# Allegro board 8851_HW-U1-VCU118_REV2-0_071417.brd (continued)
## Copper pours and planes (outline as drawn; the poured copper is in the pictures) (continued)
(no net) on TOP: 177.19,71.52 177.19,70.35 176.97,70.12 174.89,70.12 174.65,70.36 174.65,71.83 174.88,72.06 176.66,72.06
(no net) on BOTTOM: 46.3,48.76 46.3,50.44 46.09,50.64 43.5,50.64 43.41,50.55 43.41,48.66 43.46,48.61 46.15,48.61
(no net) on BOTTOM: 45.01,21.77 43.5,21.77 43.41,21.67 43.41,19.78 43.46,19.73 45.46,19.73 45.77,20.04 45.77,21.23 45.67,21.34 45.21,21.34 45.06,21.49 45.06,21.71
(no net) on BOTTOM: 187.39,51.67 181.83,51.67 181.83,49.07 187.39,49.07
(no net) on BOTTOM: 144,127.21 145.92,127.21 146.3,127.59 146.3,128.95 146.02,129.23 145.3,129.23 144.88,129.64 144.88,130.66 144.53,131.01 143.38,131.01 143.21,130.84 143.21,127.91 143.36,127.76 143.98,127.76 143.98,127.23
(no net) on BOTTOM: 195.52,16.69 194.62,15.78 191.98,15.78 191.98,14.01 192.12,13.86 196.98,13.86 197.44,14.32 197.44,16.38 197.13,16.69
(no net) on BOTTOM: 21.46,87.54 21.47,87.54 21.47,90.16 21.38,90.24 18.64,90.24 18.54,90.15 18.54,87.74 18.75,87.54
(no net) on BOTTOM: 49.36,100.55 51.1,100.55 51.43,100.88 51.43,103.01 51.14,103.3 49.38,103.3 49.11,103.02 49.11,100.81
(no net) on BOTTOM: 140.49,16.21 140.49,14.39 142.58,14.39 142.84,14.65 142.84,16.14 142.65,16.33 140.62,16.33
(no net) on BOTTOM: 42.51,33.1 40.16,33.1 40.11,33.06 40.11,18.39 40.2,18.3 42.94,18.3 43.22,18.59 43.22,19.2 42.81,19.61 42.01,19.61 41.83,19.8 41.75,19.8 41.75,31.76 42.05,32.05 42.76,32.05 42.89,32.18 42.89,32.72
(no net) on BOTTOM: 140.28,126.37 140.28,116.47 137.24,116.47 137.24,126.37
(no net) on BOTTOM: 184.95,56.96 184.95,60.77 185.07,60.89 185.33,60.89 185.58,61.15 185.58,63.05 185.71,63.18 186.22,63.18 186.47,62.93 186.47,60.26 186.98,59.75 186.98,58.86 187.61,58.23 187.61,56.96 188.97,56.96 189.99,55.93 189.99,53.87 188.65,52.52 178.63,52.52 178.1,53.05 178.1,55.42 178.38,55.7 180.97,55.7 182.22,56.96
(no net) on BOTTOM: 42.51,58.68 40.16,58.68 40.11,58.63 40.11,44.23 40.31,44.03 42.94,44.03 43.22,44.31 43.22,44.72 42.77,45.18 41.95,45.18 41.75,45.37 41.75,57.34 42.05,57.63 42.76,57.63 42.89,57.76 42.89,58.29
(no net) on BOTTOM: 139.43,24.96 137.09,24.96 137.09,28.53 137.26,28.7 138.47,28.7 138.47,27.29 138.59,27.17 139.22,27.17 139.43,26.96
(no net) on BOTTOM: 150.34,128.63 150.34,130.1 150.25,130.19 147.28,130.19 147.28,128.63 147.56,128.35 150.06,128.35
(no net) on BOTTOM: 156.23,143.36 156.23,136.75 156.21,136.75 156.21,133.31 155.48,132.58 153.21,132.58 152.46,133.33 152.46,134.67 153.69,135.9 153.69,138.78 150.7,138.78 150.55,138.93 150.55,140.46 150.9,140.81 151.79,140.81 152.42,141.45 153.69,141.45 153.69,143.12 154.25,143.68 155.91,143.68
(no net) on BOTTOM: 59.6,135.74 59.6,133.98 60.08,133.51 66.6,133.51 66.6,133.53 66.8,133.53 67.33,134.06 67.33,135.4 65.98,136.74 57.2,136.74 57.03,136.58 57.03,135.53 57.4,135.53 57.61,135.74
(no net) on BOTTOM: 232.09,60.92 228.51,60.92 227.46,59.87 227.46,58.95 228.89,57.52 228.89,54.94 228.93,54.94 230.96,52.91 232.87,52.91 233.91,53.95 233.91,59.1
(no net) on BOTTOM: 25.83,139.09 25.83,140.79 25.69,140.93 25.69,141.62 25.63,141.68 24.79,141.68 24.26,141.15 23.72,141.15 23.63,141.06 23.63,138.8 24.69,137.74 25.22,137.74 25.32,137.85 25.32,138.58
(no net) on BOTTOM: 233.05,134.9 233.05,142.09 231.75,143.38 228.63,143.38 227.48,142.24 227.48,139.55 227.13,139.19 222.45,139.19 221.54,140.11 221.54,142.87 221.23,143.18 219.23,143.18 218.82,142.78 218.82,138.43 212.57,132.18 212.57,129.95 213.8,128.72 216.37,128.72 219.41,131.75 222.17,131.75 222.43,132 222.43,132.82 223.19,133.58 231.73,133.58
(no net) on BOTTOM: 214.25,149.51 214.25,145.06 214.48,144.83 217.71,144.83 218.52,144.02 221.26,144.02 221.95,143.33 221.95,140.92 223.27,139.6 225.96,139.6 227.08,140.72 227.08,142.39 228.45,143.76 232.26,143.76 232.89,144.4 232.89,148.61 232.11,149.4 217.92,149.4 217.55,149.77 214.5,149.77
(no net) on BOTTOM: 191.11,44.7 191.11,36.17 190.93,35.99 188.06,35.99 187.58,36.47 187.58,43.11 189.56,45.08 190.73,45.08
(no net) on BOTTOM: 46.3,52.06 46.3,53.74 46.09,53.94 43.5,53.94 43.41,53.85 43.41,51.96 43.46,51.91 46.15,51.91
(no net) on BOTTOM: 61.17,128.31 60.86,128.62 58.04,128.62 57.48,128.07 57.48,123.77 58.37,122.88 60.97,122.88 61.17,123.08
(no net) on BOTTOM: 5.14,126.69 5.06,126.62 5.06,124.44 5.17,124.33 7.24,124.33 7.49,124.59 7.49,126.31 7.11,126.69
(no net) on BOTTOM: 45.45,28.37 43.5,28.37 43.41,28.28 43.41,26.38 43.46,26.34 45.61,26.34 45.75,26.48 45.75,28.07
(no net) on BOTTOM: 180.58,15.66 180.58,13.98 180.8,13.76 189.91,13.76 190.28,14.13 190.28,15.51 189.87,15.93 180.85,15.93
(no net) on BOTTOM: 20.85,140.39 20.85,135.48 20.62,135.25 17.33,135.25 16.59,135.99 16.08,135.99 15.85,136.22 15.85,140.64 16.48,141.27 17.78,141.27 18.2,141.7 18.2,143.11 19.94,143.11 20.17,142.88 21.51,142.88 21.72,142.67 21.72,141.25
(no net) on BOTTOM: 205.31,136.7 210.44,141.83 210.44,143.94 210.82,144.32 217.32,144.32 218.31,143.33 218.31,138.46 211.76,131.9 211.76,130.35 211.05,129.64 206.73,129.64 205.31,131.06
(no net) on BOTTOM: 41.63,106.01 40.61,106.01 40.5,106.13 40.5,107.48 41.17,108.15 41.17,108.56 41.38,108.76 42.14,108.76 42.37,108.53 43,108.53 43.92,107.62 43.92,106.2 43.59,105.87 41.78,105.87
(no net) on BOTTOM: 197.19,144.48 197.19,150.05 196.78,150.45 192.36,150.45 192.15,150.24 192.15,148.49 193.58,147.06 193.58,144.48
(no net) on BOTTOM: 157.23,142.59 157.23,137.46 157.49,137.21 159.9,137.21 160.28,137.59 160.28,142.59
(no net) on BOTTOM: 46.3,23.18 46.3,24.86 46.09,25.07 43.5,25.07 43.41,24.98 43.41,23.08 43.46,23.04 46.15,23.04
(no net) on BOTTOM: 137.09,20.65 139.41,20.65 139.41,18.52 139.48,18.45 139.48,14.39 137.59,14.39 136.87,15.11 136.87,18.8 137.09,19.02
(no net) on BOTTOM: 198.61,21.69 199.39,22.47 199.39,35.23 199.77,35.61 199.77,45.41 195.56,45.41 194.78,44.63 194.78,42.89 195.63,42.03 195.63,22.5 196.45,21.69
(no net) on BOTTOM: 63.2,123.2 65.41,123.2 65.65,123.45 65.65,127.99 64.98,128.66 63.12,128.66 62.79,128.33 62.79,123.62
(no net) on BOTTOM: 0.64,5.11 0.64,175.31 240.66,175.31 240.66,13.36 129.77,13.36 129.77,13.72 44.73,13.72 44.73,12.84 42.12,13.15 40.72,10.92 40.72,5.13 33.99,5.13 33.99,13.36 14.38,13.36 14.38,5.11 ; 158 cut-outs
(no net) on BOTTOM: 60.25,86.41 60.25,89.13 60.58,89.46 63.83,89.46 64.45,88.84 64.45,87.32 64.44,87.31 63.45,87.31 63.26,87.13 63.26,85.3 63.11,85.14 61.37,85.14 60.69,84.46 60.69,82.32 60.34,81.97 59.33,81.97 58.95,82.35 58.95,85.12
(no net) on BOTTOM: 65.02,82.02 65.02,85.39 64.86,85.54 64.33,85.54 64.12,85.33 64.12,84.12 63.53,83.53 61.11,83.53 61.11,81.81 61.53,81.39 64.39,81.39
(no net) on BOTTOM: 44.56,100.9 44.83,100.63 46.48,100.63 46.62,100.77 46.62,103 46.36,103.25 44.82,103.25 44.56,103
(no net) on BOTTOM: 193.23,171.89 191.54,171.89 191.22,171.58 191.22,168.88 191.33,168.77 193.33,168.77 193.56,169 193.56,171.57
(no net) on BOTTOM: 138.97,27.98 138.97,29.43 139.21,29.66 141.32,29.66 141.51,29.47 141.51,28 140.69,28 140.66,27.98 140.38,27.98 140.09,27.69 138.98,27.69 138.98,27.98
(no net) on BOTTOM: 145.15,111.05 144.49,110.39 144.49,106.81 144.67,106.63 145,106.63 145.53,106.1 145.87,106.1 145.95,106.18 145.95,106.73 145.85,106.83 145.85,108.76 146.08,108.99 146.76,108.99 146.81,109.04 146.81,110.67 146.43,111.05
(no net) on BOTTOM: 192.85,19.17 192.59,19.17 191.65,20.11 190.12,20.11 189.71,20.52 187.05,20.52 186.18,21.39 182.88,21.39 182.38,20.88 182.38,18.11 182.38,18.1 182.38,17.59 183.03,16.94 187.35,16.94 187.99,16.91 189.72,16.91 190.35,16.29 193.53,16.29 193.58,16.34 193.58,18.44
(no net) on BOTTOM: 45.59,104.32 48.64,104.32 48.9,104.57 48.9,107.11 48.64,107.37 45.59,107.37 45.34,107.11 45.34,104.57
(no net) on BOTTOM: 45.03,59.16 44.88,59.31 43.92,59.31 43.42,58.81 43.42,57.16 43.41,57.16 43.41,55.26 43.46,55.21 44.98,55.21 45.03,55.27
(no net) on BOTTOM: 195.85,57.19 195.85,51.88 196.15,51.58 200.57,51.58 200.79,51.79 200.79,53.54 199.36,54.97 199.36,56.78 198.58,57.56 196.22,57.56
(no net) on BOTTOM: 43.41,29.68 43.46,29.64 45.03,29.64 45.05,29.67 45.05,31.63 45.45,32.02 45.45,32.44 45.1,32.78 43.68,32.78 43.41,32.52
(no net) on BOTTOM: 173.95,82.15 173.95,86.23 171.97,86.23 171.97,92.84 173.95,92.84 173.95,99.19 171.97,99.19 171.97,105.5 173.98,105.5 173.98,111.48 171.97,111.48 171.97,115.07 177.68,115.07 177.68,82.15
(no net) on BOTTOM: 178.19,82.6 178.19,118.44 186.83,118.44 186.83,111.19 189.88,111.19 189.88,85.27 186.4,85.27 186.4,82.6
(no net) on 03_SIG1: 217.28,155.91 220.79,155.91 221.11,155.6 221.11,150.77 222.88,149 229.02,149 230.07,147.94 230.86,147.94 231.62,147.18 231.62,144.48 230.84,143.69 228.68,143.69 226.95,141.96 226.95,140.23 225.96,139.24 219.59,139.24 216.2,142.63 214.4,142.63 212.55,144.48 212.55,151.18
(no net) on 05_SIG2: 227.18,166.27 239.32,166.27 240.03,165.56 240.03,129.29 238.61,127.86 215.04,127.86 213.06,129.84 213.06,142.37 214.53,143.84 214.53,153.62
(no net) on 07_SIG3: 227.18,166.27 239.32,166.27 240.03,165.56 240.03,129.29 238.61,127.86 214.66,127.86 212.78,129.74 212.78,135.86 215.42,138.51 215.42,154.51
(no net) on 14_SIG4: 227.18,166.27 239.32,166.27 240.03,165.56 240.03,129.29 238.61,127.86 215.62,127.86 213.11,130.38 213.11,152.2
(no net) on 16_SIG5: 227.18,166.27 239.32,166.27 240.03,165.56 240.03,129.29 238.61,127.86 215.98,127.86 213.03,130.81 213.03,152.12
(no net) on 18_SIG6: 227.18,166.27 239.32,166.27 240.03,165.56 240.03,129.29 238.61,127.86 214.73,127.86 212.85,129.74 212.85,143.69 214.53,145.36 214.53,153.62
31N3398 on BOTTOM: 236.73,99.62 236.73,96.55 230.89,96.55 230.89,101.67 231.27,101.67 231.27,104.08 231.36,104.18 232.31,104.18 232.41,104.08 232.41,100.51 233.3,99.62
51N1061 on TOP (solid shape): 220.23,151.23 221.4,151.23 221.4,151.16 221.7,150.86 221.71,150.85 221.74,150.77 221.79,150.7 221.79,149.18 221.59,148.98 218.69,148.98 217.53,150.15 214.28,150.15 213.67,149.54 213.67,146.01 213.22,145.57 210.86,145.57 210.74,145.68 210.74,146.77 212.27,148.3 212.27,150.89 213.44,152.05 220.23,152.05
60N3562 on TOP (solid shape): 140.5,103.45 140.33,103.28 140.33,101.64 140.51,101.46 140.93,101.46 141.16,101.23 141.48,101.23 141.5,101.2 141.65,101 141.9,100.94 141.93,100.95 141.98,100.9 141.98,98.91 141.54,98.48 140.2,98.48 140.2,98.53 139.91,98.89 139.49,98.71 139.25,98.48 137.21,98.48 137.21,100.54 137.46,100.79 137.72,100.79 137.72,101.05 138.11,101.44 138.11,102.76 138.17,102.82 138.17,104.95 140.5,104.95
60N4071 on BOTTOM (solid shape): 139.41,18.52 139.48,18.45 139.48,14.39 137.59,14.39 136.87,15.11 136.87,18.8 137.07,19 137.09,19.02 137.09,20.65 139.41,20.65
60N4071 on TOP: 139.06,18.97 137.64,18.97 137.11,18.44 137.11,14.63 138.07,13.67 158.22,13.67 159.94,15.39 159.94,21.74 160.81,22.61 160.81,26.54 162.41,28.14 168.43,28.14 169.62,26.95 173.25,26.95 173.44,26.76 173.44,25.07 175,23.51 176.34,23.51 176.66,23.83 176.66,24.91 176.12,25.45 175.71,25.45 175.48,25.67 175.48,27.44 174.58,28.34 171.21,28.34 169.88,29.67 159.87,29.67 158.22,28.02 158.22,22.45 157.96,22.2 157.96,17.04 157.63,16.71 139.67,16.71 139.37,17.02 139.37,18.67
60N4071 on 05_SIG2: 180.47,22.86 180.47,14.88 179.7,14.12 176.25,14.12 174.29,16.08 174.29,24.36 175.18,25.25 175.87,25.25 176.07,25.04 176.07,23.9 176.81,23.16 180.16,23.16
61N7077 on TOP (solid shape): 205.31,49.78 205.31,45.54 206.5,44.34 206.5,41.03 205.47,40 205.47,37.24 204.22,35.99 202.21,35.99 202.21,41.4 202.62,41.81 202.62,44.27 201.98,44.91 198.04,44.91 198.04,50.32 204.76,50.32
63N3442 on BOTTOM: 13.57,116.08 11.24,116.08 10.96,116.35 10.96,118.59 11.04,118.66 11.67,118.66 12.02,118.32 13.32,118.32 13.64,117.99 13.64,116.15
68N294 on 05_SIG2: 125.65,171.11 125.65,160.62 119.41,160.62 119.41,171.11
77N4651 on TOP (solid shape): 55.75,119.53 55.75,115.56 55.63,115.49 55.52,115.41 55.5,115.4 55.27,115.4 55.27,115.17 55.26,115.15 54.95,114.25 55.27,113.34 55.27,110.09 54.95,109.21 55.23,108.32 55.25,108.29 53.31,106.35 51.54,106.35 51.51,106.38 51.51,110.59 50.72,111.38 50.72,114.08 51.29,114.64 51.29,115.41 51.01,115.69 51.01,117.05 52.02,118.06 52.02,120.29 54.99,120.29
5336N2098 on TOP: 38.79,88.21 40.13,88.21 40.28,88.06 40.28,84.71 40.23,84.66 39.12,84.66 38.68,85.09 38.68,88.11
5336N2098 on BOTTOM: 43.41,88.8 44.12,88.09 44.12,86.18 44.04,86.11 38.05,86.11 37.72,86.44 37.72,87.68 37.62,87.78 37.34,87.78 37.21,87.91 37.21,88.95 38.43,88.95 38.58,88.8
5336N2099 on BOTTOM: 47.22,88.87 52.96,88.87 53.64,88.19 53.64,84.35 52.63,83.34 49.6,83.34 49.46,83.48 49.46,84.08 48.95,84.59 47.01,84.59 46.84,84.76 46.84,88.49
COMBINED_PGOOD on TOP (solid shape): 207.06,167.28 194.77,167.28 194.77,169.88 207.06,169.88
COMBINED_PGOOD on BOTTOM (solid shape): 194.77,169.85 207.09,169.85 207.09,167.28 194.01,167.28 194.01,169.99 194.63,169.99
DDR4_C1_VTT on TOP (solid shape): outline of 648 points within 61.78,90.56 87.1,107.47
DDR4_C1_VTT on 03_SIG1: 65.06,94.19 63.27,94.19 62.84,93.76 62.84,89.46 63.31,88.99 63.31,88.16 63.88,87.59 65.54,87.59 65.64,87.69 65.64,90.43 65.96,90.75 65.96,93.3
DDR4_C2_VTT on BOTTOM: 153.97,96.9 153.16,97.71 152.68,97.71 152.38,98.02 150.22,98.02 149.94,98.3 148.26,98.3 147.47,99.09 147.47,100.96 148.67,102.16 148.67,102.64 148.87,102.84 148.87,104.38 148.67,104.59 148.67,105.67 147.57,106.77 147.1,106.77 146.89,106.55 146.89,105.94 146.76,105.82 146.41,105.82 146.35,105.87 146.35,106.5 146.76,106.91 146.76,108.16 147.06,108.46 153.88,108.46 154.24,108.09 154.24,106.17 153.64,105.57 152.59,105.57 152.32,105.31 152.32,104.06 152.52,103.87 170.89,103.87 171.58,103.18 171.58,97.28 171.2,96.9 ; 1 cut-out
FPGA_SYSMON_VCC on BOTTOM: 124.04,27.73 124.16,27.6 125.7,27.6 126.14,28.04 126.14,31.14 125.6,31.67 124.33,31.67 124.04,31.38
FPGA_SYSMON_VCC on 03_SIG1: 116.66,60.53 112.88,60.53 111.58,59.23 111.58,50.83 112.22,50.19 120.57,50.19 125.37,45.39 125.37,40.01 124.86,39.5 124.86,34.35 125.05,34.16 125.05,32.57 124.03,31.55 124.03,29.24 124.43,28.83 125.43,28.83 127.36,30.76 127.36,48.41 122.28,53.49 116.05,53.49 115.85,53.7 115.85,56.03 116.03,56.21 116.56,56.21 116.87,56.52 116.87,60.33
INPUT_GND on TOP (solid shape): outline of 395 points within 212.57,128.72 233.05,143.38
INPUT_GND on BOTTOM (solid shape): outline of 390 points within 212.57,128.72 233.05,143.38
INPUT_GND on 05_SIG2 (solid shape): outline of 3889 points within 213.06,127.86 240.03,166.27
INPUT_GND on 07_SIG3 (solid shape): outline of 3582 points within 212.78,127.86 240.03,166.27
INPUT_GND on 14_SIG4 (solid shape): outline of 3965 points within 213.11,127.86 240.03,166.27
INPUT_GND on 16_SIG5 (solid shape): outline of 3992 points within 213.03,127.86 240.03,166.27
INPUT_GND on 18_SIG6 (solid shape): outline of 3950 points within 212.85,127.86 240.03,166.27
INPUT_GND on 03_SIG1: 227.18,166.27 239.32,166.27 240.03,165.56 240.03,132.44 235.46,127.86 215.04,127.86 213.06,129.84 213.06,138.58 213.31,138.84 226.26,138.84 227.36,139.93 227.36,141.76 228.83,143.23 231.6,143.23 232.03,143.66 232.03,147.57 229.13,150.47 222.99,150.47 221.34,152.12 221.34,157.48 222.39,158.53 222.39,161.48
INPUT_GND on 20_SIG7: 232.89,166.27 239.32,166.27 240.03,165.56 240.03,129.29 238.61,127.86 214.73,127.86 212.85,129.74 212.85,142.93 214.43,144.5 220.04,144.5 225.37,149.83 225.37,155.24 231.14,161.01 231.14,164.52
MASTER_SW_12V on TOP (solid shape): outline of 104 points within 223.8,155.78 231.6,160.15
MGTAVCC on TOP (solid shape): 142.74,135.06 142.74,131.3 132.2,131.3 132.09,131.41 132.09,133.73 134.21,133.73 137.62,137.15 140.65,137.15
MGTAVCC_FPGA on TOP (solid shape): outline of 85 points within 125.55,135.36 133.96,142.29
MGTAVCC_FPGA on TOP, BOTTOM: 98.76,30.4 98.76,32.31 98.98,32.54 98.98,33.3 98.86,33.43 94.46,33.43 94.36,33.32 94.36,32.56 94.54,32.38 94.54,30.4
MGTAVCC_FPGA on 11_PWR2: 137.36,141.68 137.36,141.12 123.42,127.18 123.42,95.63 129.59,89.46 129.59,82.52 128.27,81.2 125.88,81.2 124.64,79.96 124.64,79.86 123.32,78.54 121.64,78.54 121.03,77.93 113.26,77.93 109.04,82.14 105.69,82.14 102.57,79.02 102.57,53.34 104.27,51.64 111.48,51.64 113.06,53.21 121.54,53.21 122.55,52.2 130.28,52.2 132.97,49.5 133.48,49.35 133.48,33.96 131.06,31.55 94.74,31.55 94.11,32.18 94.11,34.72 92.96,35.86 84.61,35.86 81.97,38.51 81.97,104.77 82.25,105.05 100.51,105.05 104.83,109.38 104.83,135.23 113,143.41 135.64,143.41
MGTAVCC_VX2 on TOP (solid shape): 147.3,143.21 147.3,142.94 147.3,142.88 147.3,141.99 147.3,141.94 147.3,141.88 147.3,140.99 147.3,140.94 147.3,140.88 147.3,139.99 147.3,139.94 147.3,139.88 147.3,139.37 146.94,139.37 146.78,139.34 146.65,139.25 146.42,139.25 146.29,139.34 146.13,139.37 145.19,139.37 145.08,139.48 145.08,140.22 144.44,140.87 143.18,140.87 141.86,139.55 137.64,139.55 137.46,139.73 137.46,142.69 138.17,143.39 147.12,143.39
MGTAVTT on TOP (solid shape): 186.02,74.5 186.02,68.75 185.14,67.87 181.08,67.87 180.91,68.04 180.91,75.81 181.01,75.91 184.61,75.91
MGTAVTT_FPGA on TOP (solid shape): outline of 93 points within 171.7,73.4 179.43,78.61
MGTAVTT_FPGA on 12_PWR3: 142.2,84.47 141.5,83.77 134.9,83.77 130.56,79.43 130.56,68.38 131.75,67.18 142.49,67.18 147.55,72.24 167.03,72.24 168.48,73.69 168.48,82.78 167.87,83.39 167.87,86.23 170.18,88.54 170.18,97.31 168.48,99.01 168.48,105.82 166.65,107.65 166.65,115.6 167.34,116.28 181.79,116.28 191.16,106.91 191.16,65.53 178.79,53.16 153.13,53.16 151.11,55.19 130.94,55.19 130.78,55.03 130.78,54.59 130.95,54.42 150.99,54.42 153.21,52.2 153.21,36.7 148.72,32.21 131.18,32.21 128.44,29.47 120.85,29.47 119.78,30.54 117.53,30.54 116.17,29.18 110.8,29.18 108.89,31.08 84.77,31.08 83.58,32.27 83.58,44.98 85.49,46.89 92.08,46.89 92.77,47.57 99.92,47.57 100.62,48.27 100.62,48.88 101.35,49.61 103.38,49.61 105.2,51.43 105.2,58.2 107.21,60.21 107.21,65.51 105,67.72 105,80.29 102.31,82.98 93.62,82.98 92.74,83.87 92.74,100.86 95.63,103.76 117.58,103.76 117.68,103.86 129.11,103.86 142.2,90.77
MGTAVTT_VX2 on TOP (solid shape): 191.47,72.69 191.47,66.8 190.66,66 190.66,65.59 190.53,65.59 190.53,64.07 190.15,63.69 186.6,63.69 186.44,63.84 186.44,63.86 186.41,63.97 186.34,64.07 186.34,64.33 186.42,64.46 186.44,64.61 186.44,65.57 186.47,65.59 186.47,67.5 188.43,69.45 188.43,72.87 191.28,72.87
MGTVCCAUX_L on TOP (solid shape): 136.46,98.48 134.78,98.48 134.64,98.65 134.45,98.76 134.44,98.76 134.32,98.88 134.19,98.88 134.11,98.96 134.11,99.97 134.19,100.05 134.25,100.05 134.57,100.15 134.78,100.41 136.46,100.41
MGTVCCAUX_L on BOTTOM: 109.9,100.33 112.35,100.33 112.7,99.98 112.7,96.39 116.84,92.25 119.63,92.25 121.44,94.06 121.44,96.93 120.6,97.76 120.6,98.34 120.6,98.35 120.6,98.48 120.83,98.7 124.13,98.7 127.48,102.06 127.48,103.91 128.17,104.6 136.14,104.6 137.67,103.07 137.67,99.69 136.6,98.63 134.32,98.63 134.01,98.93 134.01,100.2 134.57,100.76 134.57,102.59 134.14,103.02 131.01,103.02 130.48,102.49 130.48,96.75 122.78,89.05 122.78,83.03 122.81,83.01 122.81,81.58 121.54,80.31 113.38,80.31 108.63,85.06 108.63,91.2 102.88,96.95 102.88,98.85 103.74,99.71 104.37,99.71 105.35,98.74 109.07,98.74 109.56,99.23 109.56,99.99
MGTVCCAUX_PGOOD on 16_SIG5: 199.69,172.18 199.69,151.33 207.51,151.33 207.51,172.18
MGTVCCAUX_R on BOTTOM (solid shape): 142.84,16.14 142.84,14.65 142.58,14.39 140.49,14.39 140.49,16.21 140.62,16.33 142.65,16.33
MGTVCCAUX_R on 05_SIG2: 121.52,51.49 110.08,51.49 109.63,51.03 109.63,46.86 110.3,46.19 116.21,46.19 116.46,45.93 116.46,42.45 111.12,37.11 111.12,32 112.08,31.03 113.97,31.03 119.8,36.87 119.8,40.86 120.94,42 120.94,46.14 121.89,47.08 121.89,51.12
MGTVCCAUX_R on 20_SIG7: 114.38,33.58 110.19,33.58 109.65,33.05 109.65,23.62 113.64,19.63 118.49,19.63 119.37,18.75 119.37,17.18 121.52,15.04 126.75,15.04 127.61,14.17 142.34,14.17 143.03,14.86 143.03,16.89 142.29,17.63 141.31,17.63 138.95,19.99 135.03,19.99 133.93,18.9 130.28,18.9 127.82,21.35 125.69,21.35 118.67,28.37 116.94,28.37 114.76,30.56 114.76,33.2
Net_127 on BOTTOM (solid shape): outline of 220 points within 58.36,74.18 64.71,80.53
Net_128 on BOTTOM (solid shape): outline of 220 points within 22.57,74.18 28.92,80.53
Net_129 on TOP (solid shape): outline of 220 points within 58.36,74.18 64.71,80.53
Net_130 on TOP (solid shape): outline of 220 points within 22.57,74.18 28.92,80.53
Net_133 on TOP (solid shape): 49.35,81.52 47.89,81.52 47.54,81.87 47.54,82.94 49.35,82.94
Net_134 on TOP (solid shape): 39.74,81.87 39.39,81.52 37.93,81.52 37.93,82.94 39.74,82.94
QSFP1_VCC1_FILT on TOP (solid shape): 65.86,29.84 65.86,28.47 65.79,28.4 63.4,28.4 63.39,28.41 62.97,28.41 62.83,28.55 62.83,29.81 63.05,30.02 65.68,30.02
QSFP1_VCC1_FILT on BOTTOM (solid shape): 45.45,32.44 45.45,32.02 45.05,31.63 45.05,29.67 45.03,29.64 43.46,29.64 43.41,29.68 43.41,32.52 43.68,32.78 45.1,32.78
QSFP1_VCC1_FILT on 07_SIG3: 55.04,26.57 57.15,26.57 58.72,28.14 64.97,28.14 65.46,28.63 65.46,29.87 62.15,33.17 44.58,33.17 43.41,32 43.41,26.77 43.66,26.52 54.99,26.52
QSFP1_VCCRX_FILT on TOP (solid shape): 66.04,36.41 66.04,35.8 65.68,35.43 62.79,35.43 62.66,35.56 62.66,36.83 62.81,36.98 65.48,36.98
QSFP1_VCCRX_FILT on BOTTOM (solid shape): 46.3,24.86 46.3,23.18 46.15,23.04 43.46,23.04 43.41,23.08 43.41,24.98 43.5,25.07 46.09,25.07
QSFP1_VCCRX_FILT on 07_SIG3: 48.39,25.78 43.33,25.78 42.21,26.9 42.21,32.38 43.74,33.91 63.32,33.91 64.21,34.8 64.21,37.19 61.9,39.5 41.48,39.5 38.46,36.47 38.46,25.45 41.33,22.58 46.74,22.58 48.39,24.23
QSFP1_VCCTX_FILT on BOTTOM (solid shape): 45.75,28.07 45.75,26.48 45.61,26.34 43.46,26.34 43.41,26.38 43.41,28.28 43.5,28.37 45.45,28.37
QSFP1_VCCTX_FILT on 20_SIG7: 45.54,24.97 64.06,24.97 66.8,27.71 66.8,28.54 61.55,33.8 47.52,33.8 44.88,31.15 44.88,25.63
QSFP2_VCC1_FILT on BOTTOM (solid shape): 45.03,59.16 45.03,55.27 44.98,55.21 43.46,55.21 43.41,55.26 43.41,57.16 43.42,57.16 43.42,58.81 43.92,59.31 44.88,59.31
QSFP2_VCC1_FILT on TOP: 63.55,56.11 66.88,56.11 67.01,56.24 67.01,57.53 66.95,57.58 66.32,57.58 65.63,56.9 63.47,56.9 63.4,56.82 63.4,56.26
QSFP2_VCC1_FILT on 07_SIG3: 67.16,57.63 67.16,52.98 66.32,52.15 47.62,52.15 47.61,52.16 46.06,52.16 44.02,54.2 44.02,59.28 44.42,59.69 65.1,59.69
QSFP2_VCCRX_FILT on BOTTOM (solid shape): 46.3,50.44 46.3,48.76 46.15,48.61 43.46,48.61 43.41,48.66 43.41,50.55 43.5,50.64 46.09,50.64
QSFP2_VCCRX_FILT on TOP: 63.53,63.27 65.99,63.27 66.34,63.63 66.34,65.05 66.12,65.28 63.75,65.28 63.32,64.85 63.32,63.47
QSFP2_VCCRX_FILT on 07_SIG3: 45.82,47.57 42.7,47.57 37.39,52.88 37.39,66.07 38.15,66.83 59.87,66.83 61.14,65.56 65.81,65.56 66.17,65.2 66.17,64.29 65.89,64.01 65.89,62.03 65.53,61.67 64.59,61.67 63.2,60.27 47.7,60.27 46.15,61.82 44.63,61.82 43.64,60.83 43.64,53.75 45.97,51.41 48.31,51.41 48.44,51.28 48.44,50.77 48.31,50.65 47.98,50.65 46.63,49.3 46.63,48.39
QSFP2_VCCTX_FILT on TOP (solid shape): 66.01,55.1 66.01,54.29 65.85,54.14 63.76,54.14 63.48,54.42 63.48,55.3 63.78,55.6 65.51,55.6
QSFP2_VCCTX_FILT on BOTTOM (solid shape): 45.9,53.94 46.05,53.77 46.26,53.67 46.3,53.66 46.3,52.06 46.15,51.91 43.46,51.91 43.41,51.96 43.41,53.85 43.5,53.94
QSFP2_VCCTX_FILT on 20_SIG7: 44.6,51.66 46.1,50.17 60.73,50.17 65.83,55.27 65.85,56.86 65.85,58.44 64.71,59.57 46.39,59.57 44.6,57.78
RLD3_C3_VTERM_0V6 on BOTTOM (solid shape): 57.81,136.6 65.36,136.6 65.5,136.74 65.98,136.74 67.33,135.4 67.33,134.06 66.8,133.53 66.6,133.53 66.6,133.51 60.08,133.51 59.89,133.69 59.89,133.73 59.6,134.02 59.6,135.74 58.01,135.74 57.89,135.75 57.78,135.74 57.61,135.74 57.4,135.53 57.21,135.53 57.21,136.35 57.03,136.53 57.03,136.58 57.2,136.74 57.67,136.74
RLD3_C3_VTERM_0V6 on 11_PWR2: 62.69,140.11 65.93,140.11 71.31,134.73 104.18,134.73 104.46,134.46 104.46,109.48 100.42,105.44 75.64,105.44 75.29,105.79 75.29,123.14 74.12,124.31 59.94,124.31 59.4,124.85 59.4,136.82
SI5328_VCC on TOP (solid shape): 86.52,29.51 88.01,29.51 88.01,27.9 87.74,27.63 85.83,27.63 85.4,27.2 84.91,27.2 84.85,27.25 84.85,29.64 84.92,29.71 86.32,29.71
SI5328_VCC on BOTTOM: 82.3,25.33 80.91,25.33 80.57,25.66 80.57,28.22 81.97,29.62 87.33,29.62 89.97,26.97 89.97,23.72 89.26,23.02 88.58,23.02 88.12,23.48 88.12,26.02 87.47,26.67 82.51,26.67 82.42,26.58 82.42,25.92 82.42,25.92 82.42,25.45
SYS1V0_LX on TOP (solid shape): 17.87,125.44 17.86,125.41 17.79,124.87 18.01,124.37 18.01,123 17.89,122.81 17.81,122.6 17.81,122.58 17.77,122.54 16.49,122.54 16.41,122.62 16,122.62 15.75,122.37 15.75,122.15 15.63,122.03 14.62,122.03 14.62,125.24 14.62,125.24 14.62,125.49 17.82,125.49
SYS2V5_LX on TOP (solid shape): 61.11,123.09 60.71,122.69 60.33,122.69 60.07,122.44 60.07,122.28 60.06,122.17 60.06,122.07 60.06,122.04 59.82,121.8 59.46,121.8 59.19,122.08 59.19,122.31 58.42,123.07 58.42,124.37 58.43,124.38 58.47,124.61 58.43,124.83 58.42,124.84 58.42,127.97 59.06,128.61 61.11,128.61
SYS_1V0 on TOP (solid shape): 9.7,125.79 9.79,125.72 9.76,125.6 10.35,123.76 10.94,125.6 10.9,125.72 11,125.79 12.93,125.79 13.44,125.28 13.44,121.97 12.74,121.27 11.61,121.27 11.61,121.31 11.23,121.63 10.85,121.31 10.85,121.27 6.51,121.27 6.38,121.14 4.22,121.14 4.22,123.75 4.35,123.88 6.72,123.88 6.95,124.1 6.98,124.1 6.98,124.13 7.49,124.65 7.57,124.71 7.64,124.79 8.64,125.79
SYS_1V0 on BOTTOM (solid shape): 7.49,126.31 7.49,124.59 7.24,124.33 5.17,124.33 5.08,124.42 5.08,126.64 5.14,126.69 7.11,126.69
SYS_1V0 on 09_PWR1: 1.27,132.03 6.15,132.03 6.63,132.51 6.63,142.11 15.16,150.65 39.61,150.65 41.62,148.64 41.62,145.15 43.56,143.21 43.56,139.5 25.5,121.44 11.68,121.44 11.33,121.08 11.33,118.95 13.08,117.2 15.19,117.2 18.24,114.15 28.65,114.15 29.07,114.57 30.61,114.57 30.89,114.29 30.89,109.37 29.64,108.13 1.27,108.13
SYS_1V8 on TOP (solid shape): 20.4,144.07 19.84,143.52 13.14,143.52 12.93,143.73 12.93,146.03 20.4,146.03
SYS_1V8 on TOP (solid shape): 6.76,127.4 6.76,124.48 6.64,124.37 5.26,124.37 5.21,124.42 5.21,127.25 5.5,127.55 6.61,127.55
SYS_1V8 on TOP (solid shape): 25.9,146.45 25.9,144.87 25.81,144.78 22.84,144.78 22.5,144.45 21.21,144.45 20.95,144.7 20.95,146.21 21.21,146.47 25.88,146.47
SYS_1V8 on BOTTOM (solid shape): 38.72,109.53 38.72,108.16 38.4,107.84 38.4,106.5 37.62,106.5 37.1,107.02 37.1,109.6 37.18,109.68 38.57,109.68
SYS_1V8 on BOTTOM: 22.33,146.35 20.7,146.35 20.07,145.72 20.07,143.5 20.19,143.38 21.43,143.38 21.6,143.55 21.6,144.4 21.83,144.63 22.35,144.63 22.58,144.85 22.58,146.11
SYS_1V8 on BOTTOM: 12.98,114.17 13.54,113.61 13.54,101.85 12.19,100.51 9.96,100.51 9.19,101.27 9.19,113.28 9.63,113.72 11.61,113.72 12.07,114.17
SYS_1V8 on 11_PWR2: 240.03,174.65 240.03,14 13.74,14 13.74,5.74 1.27,5.74 1.27,174.65
SYS_1V8 on 14_SIG4: 50.01,141.76 46.96,144.81 42.52,144.81 40.34,142.62 40.34,139.09 38.23,136.98 36.63,136.98 35.86,136.22 35.86,130.66 36.93,129.59 45.9,129.59 50.01,133.71
SYS_2V2 on TOP (solid shape): outline of 113 points within 47.35,133.78 53.72,137.26
SYS_2V2 on 20_SIG7: 58.73,140.71 57.79,141.65 52.83,141.65 47.22,136.04 39.77,136.04 38.7,134.97 38.7,131.1 40.03,129.77 56.72,129.77 58.73,131.78
SYS_2V5 on TOP (solid shape): outline of 85 points within 62.62,123.29 68.45,128.66
SYS_2V5 on BOTTOM (solid shape): 65.65,127.99 65.65,123.45 65.41,123.2 63.2,123.2 62.79,123.62 62.79,128.33 63.12,128.66 64.98,128.66
SYS_2V5 on BOTTOM: 99.28,116.88 98.93,117 98.79,117.35 98.79,117.4 98.67,117.4 98.67,117.35 98.6,117.08 98.38,116.91 98.32,116.83 98.35,116.74 98.7,116.39 101.88,116.39 101.88,112.39 102.57,111.71 103.17,111.71 103.81,111.07 103.81,106.78 101.42,104.39 86.4,104.39 85.09,105.7 66.51,105.7 63.46,108.75 63.46,117.66 64.27,118.46 64.27,121.73 62.79,123.21 62.79,128.59 63.4,129.21 65.31,129.21 65.75,128.76 68.07,128.76 69.18,127.64 84.74,127.64 86.24,126.14 102.72,126.14 103.54,125.32 103.54,122.18 101.95,122.18 101.95,120.4 100.43,120.4 100.43,116.57 99.63,116.57 99.31,116.89 ; 7 cut-outs
SYS_2V5 on 09_PWR1: 81.21,103.44 81.21,91.29 79.5,89.58 79.5,86.26 81.21,84.55 81.21,53.77 82.57,52.42 98.03,52.42 98.07,52.38 114.88,52.38 115.27,51.99 115.27,44.7 116.79,43.18 168.45,43.18 168.81,42.82 168.81,31.07 167.77,30.03 149.42,30.03 146.18,33.27 67.84,33.27 66.87,34.25 66.87,60.64 65.56,61.95 65.56,82.25 52.73,95.07 52.73,115.62 55.73,118.62 60.49,118.62 63.1,121.23 63.1,127.71 64.7,129.31 68.23,129.31 68.8,128.73 68.8,125.22 67.34,123.76 67.34,110.54 67.75,110.13 68.3,110.13 68.68,110.51 70.46,110.51 70.66,110.31 70.66,109.85 71.06,109.45 76.44,109.45 76.62,109.26 76.62,108.48 76.89,108.22 77.89,108.22 79.11,109.44 80.76,109.44 81.05,109.73 81.05,110.32 81.5,110.77 84.75,110.77 85.56,111.58 87.41,111.58 87.54,111.44 87.54,110.05 87.94,109.65 99.22,109.65 99.68,110.11 99.68,111.35 99.99,111.66 102.52,111.66 102.61,111.56 102.61,107.77 99.11,104.27 82.04,104.27
SYS_2V5 on 16_SIG5: 168.12,95.43 157.44,95.43 155.06,93.06 155.06,35.57 155.7,34.94 168.48,34.94 169.18,35.64 169.18,94.37
SYS_2V5 on 20_SIG7: 0.64,109.65 0.64,154.99 2.92,157.28 40.46,157.28 42.32,155.42 63.4,155.42 65.3,153.52 70.26,153.52 70.48,153.29 70.48,136.6 67.56,133.68 67.56,119.79 62.69,114.91 57.3,114.91 57.25,114.96 56.64,114.96 55.73,115.87 55.73,127.97 60.15,132.38 60.15,142.14 58.42,143.87 41.94,143.87 40.47,142.41 29.65,142.41 25.2,137.95 25.2,135.41 23.11,133.32 19.71,133.32 17.17,130.78 17.17,127.03 25.15,119.05 25.15,116.69 27.08,114.76 31.52,114.76 32.56,113.72 32.56,111.81 29.31,108.56 29.31,107.4 27.3,105.4 24.22,105.4 24.19,105.37 10.3,105.37 7.09,108.58 1.7,108.58
SYSCTLR_AGND on TOP (solid shape): 26.32,137.66 27.36,137.66 27.36,137.46 27.94,137.46 28.19,137.21 28.19,135.56 28.1,135.47 25.76,135.47 25.76,137.52 26.12,137.87 26.32,137.87
SYSCTLR_AGND on BOTTOM (solid shape): 25.69,141.62 25.69,140.93 25.83,140.79 25.83,139.09 25.54,138.8 25.52,138.8 25.52,138.78 25.32,138.58 25.32,137.85 25.22,137.74 24.69,137.74 24.28,138.15 24.28,138.17 24.17,138.45 23.9,138.56 23.88,138.56 23.63,138.8 23.63,141.06 23.72,141.15 24.26,141.15 24.79,141.68 25.63,141.68
SYSCTLR_AGND on 16_SIG5: 27.61,140.45 17.02,140.45 16.04,139.47 16.04,134.37 16.64,133.77 27.38,133.77 28.12,134.5 28.12,139.95
SYSCTLR_VREF on TOP: 27.48,141.44 28.01,140.91 28.01,139.53 27.91,139.42 26.51,139.42 26.11,139.82 26.11,141.38 26.18,141.44
SYSCTLR_VREF on BOTTOM: 27.97,141.44 28.16,141.26 28.16,139.67 27.91,139.42 26.51,139.42 26.39,139.54 26.39,140.59 26.14,140.85 26.14,141.3 26.28,141.44
SYSMON_AGND on BOTTOM: 115.93,59.13 116.48,59.13 116.99,58.62 121.44,58.62 121.81,58.25 121.81,55.25 127.41,49.64 131.54,49.64 131.77,49.42 131.77,40.27 129.98,38.48 126.33,38.48 124.2,36.35 124.2,32.09 122.66,30.54 122.66,29.39 122.89,29.16 123.62,29.16 123.7,29.08 123.7,27.71 123.6,27.61 121.32,27.61 120.95,27.98 120.95,32.25 122.17,33.47 122.17,36.39 126.5,40.72 127.08,40.72 127.97,41.61 127.97,44.09 127.01,45.05 119.29,45.05 118.64,45.69 118.64,53.21 118.74,53.31 118.74,55.4 117.86,56.29 116,56.29 115.7,56.59 115.7,58.9
SYSMON_VCCADC on 07_SIG3: 28.77,131.02 31.8,131.02 32.03,131.25 32.03,139.24 30.91,140.36 19.34,140.36 17.44,138.46 17.44,134.59 17.85,134.17 19.53,134.17 19.55,134.19 22.12,134.19 22.43,133.88 25.91,133.88
USB_FLTR on 03_SIG1: 7.59,73.84 14.12,73.84 15.62,72.34 15.62,64.67 14.71,63.75 9.14,63.75 6.99,65.91 6.99,73.23
USB_POWERED_VIO on 05_SIG2: 9.3,73.56 12.04,73.56 16.05,69.55 16.05,64.74 15.16,63.86 9.63,63.86 7.95,65.53 7.95,72.21
UTIL_1V35 on TOP (solid shape): outline of 90 points within 45.47,100.58 51.72,108.13
UTIL_1V35 on BOTTOM (solid shape): 48.9,107.11 48.9,104.57 48.64,104.32 45.59,104.32 45.34,104.57 45.34,107.11 45.59,107.37 48.64,107.37
UTIL_1V35 on BOTTOM (solid shape): 51.43,103.01 51.43,100.88 51.1,100.55 49.36,100.55 49.11,100.81 49.11,103.02 49.38,103.3 51.14,103.3
UTIL_1V35 on 09_PWR1: 69.11,124.99 101.65,124.99 102.62,124.03 102.62,112.27 102.39,112.04 99.82,112.04 99.29,111.51 99.29,110.52 98.81,110.03 88.75,110.03 88.42,110.36 88.42,111.18 87.63,111.96 85.34,111.96 84.53,111.15 81.28,111.15 80.67,110.54 80.67,109.88 80.59,109.8 78.92,109.8 77.8,108.69 77.19,108.69 77.01,108.86 77.01,109.4 76.58,109.83 71.22,109.83 71.04,110.01 71.04,110.46 70.61,110.9 68.53,110.9 68.22,110.59 68.03,110.59 67.73,110.9 67.73,123.61
UTIL_1V35 on 11_PWR2: 53.95,123.93 73.94,123.93 74.88,122.99 74.88,106.07 74.24,105.44 52.83,105.44 50.77,103.38 47.8,103.38 44.73,106.45 44.73,118.19 45.19,118.64 48.67,118.64
UTIL_1V35_FET_SWITCH on TOP (solid shape): 48.36,108.1 42.47,108.1 42.47,109.92 42.47,109.92 42.47,110.77 42.6,110.89 45.14,110.89 45.14,113.05 46.03,113.94 48.36,113.94
UTIL_1V35_FET_SWITCH on BOTTOM (solid shape): 48.36,108.1 42.47,108.1 42.47,109.92 42.47,109.92 42.47,110.77 42.6,110.89 45.14,110.89 45.14,113.05 45.62,113.53 45.62,114.14 46.05,114.58 48.36,114.58
UTIL_1V35_FET_SWITCH on 03_SIG1 (solid shape): 48.36,108.1 42.47,108.1 42.47,109.92 42.47,109.92 42.47,110.77 42.6,110.89 45.14,110.89 45.14,113.05 45.62,113.53 45.62,114.14 46.05,114.58 48.36,114.58
UTIL_1V35_FET_SWITCH on 05_SIG2 (solid shape): 48.36,108.1 42.47,108.1 42.47,109.92 42.47,109.92 42.47,110.77 42.6,110.89 45.14,110.89 45.14,113.05 45.62,113.53 45.62,114.14 46.05,114.58 48.36,114.58
UTIL_1V35_FET_SWITCH on 07_SIG3 (solid shape): 48.36,108.1 42.47,108.1 42.47,109.92 42.47,109.92 42.47,110.77 42.6,110.89 45.14,110.89 45.14,113.05 45.62,113.53 45.62,114.14 46.05,114.58 48.36,114.58
UTIL_1V35_FET_SWITCH on 14_SIG4 (solid shape): 48.36,108.1 42.47,108.1 42.47,109.92 42.47,109.92 42.47,110.77 42.6,110.89 45.14,110.89 45.14,113.05 45.62,113.53 45.62,114.14 46.05,114.58 48.36,114.58
UTIL_1V35_FET_SWITCH on 16_SIG5 (solid shape): 48.36,108.1 42.47,108.1 42.47,109.92 42.47,109.92 42.47,110.77 42.6,110.89 45.14,110.89 45.14,113.05 45.62,113.53 45.62,114.14 46.05,114.58 48.36,114.58
UTIL_1V35_FET_SWITCH on 18_SIG6 (solid shape): 48.36,108.1 42.47,108.1 42.47,109.92 42.47,109.92 42.47,110.77 42.6,110.89 45.14,110.89 45.14,113.05 45.62,113.53 45.62,114.14 46.05,114.58 48.36,114.58
UTIL_1V35_FET_SWITCH on 20_SIG7 (solid shape): 48.36,108.1 42.47,108.1 42.47,109.92 42.47,109.92 42.47,110.77 42.6,110.89 45.14,110.89 45.14,113.05 45.62,113.53 45.62,114.14 46.05,114.58 48.36,114.58
UTIL_3V3 on TOP (solid shape): 64.63,120.84 61.93,120.84 61.93,122.87 64.63,122.87
UTIL_3V3 on TOP (solid shape): 65.86,34.04 65.86,31.47 65.66,31.27 63.42,31.27 63.16,31.54 63.16,33.89 63.46,34.18 65.72,34.18
UTIL_3V3 on TOP (solid shape): 88.02,32.03 88.02,30.19 87.96,30.14 84.89,30.14 84.69,30.33 84.69,32.01 85.14,32.46 87.58,32.46
UTIL_3V3 on TOP (solid shape): 63.67,52.91 65.89,52.91 66.01,52.79 66.01,51.29 65.76,51.05 63.41,51.05 63.2,51.25 63.2,52.61 63.51,52.92 63.67,52.92
UTIL_3V3 on TOP (solid shape): 141.35,113.08 141.35,111.65 140.61,110.91 140.51,110.91 140.51,110.81 140.5,110.79 140.5,109.26 138.16,109.26 138.16,110.87 138.83,111.54 139.27,111.54 139.28,111.55 139.3,111.55 139.77,112.01 139.77,112.03 139.88,112.15 139.88,113.3 141.13,113.3
UTIL_3V3 on TOP (solid shape): 65.71,62.18 65.74,62.23 65.8,62.22 65.86,62.15 65.86,58.24 65.74,58.12 63.4,58.12 63.16,58.35 63.16,62 63.34,62.18 63.45,62.2 63.51,62.1 63.51,62.05 65.71,62.05
UTIL_3V3 on TOP (solid shape): 162.42,135.28 163.13,135.28 163.13,133.77 161.73,132.38 161.73,129.01 161.65,128.93 160.5,128.93 160.46,128.97 160.46,131.73 160.57,131.84 160.78,131.84 161.09,132.14 161.09,133.22 161.26,133.39 161.65,133.39 161.92,133.66 161.92,134.31 161.94,134.33 162.02,134.39 162.09,134.48 162.24,134.63 162.24,135.18 162.27,135.26 162.36,135.28
UTIL_3V3 on TOP (solid shape): 173.64,52.13 173.64,51.9 173.78,51.76 173.78,51.72 173.96,51.53 174.79,51.53 175.19,51.13 175.19,50.41 175.47,50.12 176.04,50.12 176.12,50.09 176.14,50.01 176.14,49.94 176.14,49.21 176.14,49.19 176.11,49.11 176.04,49.08 174.79,49.08 173.23,50.63 169.54,50.63 169.42,50.75 169.42,52 169.59,52.16 173.61,52.16
UTIL_3V3 on TOP (solid shape): 48.84,141.96 48.84,140.99 48.67,140.67 48.84,140.34 48.84,139.2 48.15,138.51 46.92,138.51 46.92,138.86 46.89,139.05 46.79,139.21 46.79,139.47 46.69,139.47 46.69,140.87 46.9,141.08 47.71,141.08 47.71,141.1 48.01,141.1 48.01,142.04 48.13,142.16 48.64,142.16
UTIL_3V3 on TOP (solid shape): 209.68,34.78 209.68,31.8 209.4,31.52 204.7,31.52 203.96,30.78 202.31,30.78 202.31,30.83 201.77,31.68 200.77,31.66 200.67,31.65 200.62,31.74 200.62,33.37 201.59,34.34 204.27,34.34 204.38,34.23 205.1,34.23 205.78,34.91 205.78,34.91 205.84,34.98 209.48,34.98
UTIL_3V3 on BOTTOM (solid shape): 140.28,116.47 137.24,116.47 137.24,126.37 140.28,126.37
UTIL_3V3 on BOTTOM (solid shape): 193.56,171.57 193.56,169 193.33,168.77 191.33,168.77 191.22,168.88 191.22,171.58 191.54,171.89 193.23,171.89
UTIL_3V3 on BOTTOM (solid shape): 138.47,27.29 138.59,27.17 139.22,27.17 139.43,26.96 139.43,24.96 137.09,24.96 137.09,28.53 137.26,28.7 138.47,28.7
UTIL_3V3 on BOTTOM (solid shape): 42.09,107.72 43.82,107.72 43.92,107.62 43.92,106.2 43.59,105.87 41.78,105.87 41.71,105.94 41.71,106.2 40.67,106.2 40.67,107.64 41.17,108.15 41.17,108.56 41.38,108.76 42.09,108.76
UTIL_3V3 on BOTTOM (solid shape): 45.06,21.71 45.06,21.49 45.21,21.34 45.67,21.34 45.77,21.23 45.77,20.04 45.54,19.81 45.52,19.81 45.4,19.79 45.3,19.73 43.46,19.73 43.41,19.78 43.41,21.67 43.5,21.77 45.01,21.77
UTIL_3V3 on TOP: 62.93,151.38 62.41,150.86 62.41,149.02 62.82,148.61 64.84,148.61 65.25,148.2 73.47,148.2 73.79,148.51 73.79,150.55 72.95,151.38
UTIL_3V3 on BOTTOM: 117.14,120.83 123.51,120.83 127.94,116.4 131.03,116.4 136.3,111.12 138.76,111.12 139.85,112.22 141.25,112.22 141.71,111.76 141.71,107.06 142.04,106.73 142.24,106.73 142.24,104.32 141.99,104.06 138.84,104.06 138.46,104.44 138.46,105.87 137.21,107.11 135.99,107.11 135.48,106.6 129.77,106.6 125.96,110.41 118.72,110.41 115.9,113.23 115.9,119.58
UTIL_3V3 on BOTTOM: 226.97,96.44 230.15,96.44 230.4,96.7 230.4,98.93 230.15,99.19 226.97,99.19 226.72,98.93 226.72,96.7
UTIL_3V3 on BOTTOM: 45.01,47.34 43.5,47.34 43.41,47.25 43.41,45.35 43.46,45.31 45.46,45.31 45.77,45.62 45.77,46.81 45.67,46.91 45.21,46.91 45.06,47.06 45.06,47.29
UTIL_3V3 on BOTTOM: 49.69,96.42 42.27,96.42 41.91,96.06 41.91,95.11 41.91,95.1 41.91,94.81 40.68,93.58 40.68,91.75 40.68,91.74 51.72,91.74 51.73,91.75 51.73,93.93 51.19,94.47 50.52,94.47 50.3,94.69 50.3,95.81
UTIL_3V3 on 03_SIG1: 25.12,118.31 30.91,118.31 31.6,117.63 31.6,115.9 31.04,115.34 28.88,115.34 27.89,114.35 25.22,114.35 24.46,115.11 24.46,117.65
UTIL_3V3 on 07_SIG3: 139.4,126.24 139.7,125.93 139.7,118.67 142.85,115.52 144.96,115.52 145.92,116.48 145.92,121.03 144.55,122.4 144.55,123.8 147.12,126.36 147.12,128.52 147.88,129.29 163.7,129.29 164.31,128.68 164.31,118.97 159.77,114.43 150.6,114.43 146.25,110.08 140.49,110.08 140.34,109.93 137.19,109.93 136.35,110.77 136.35,125.76 136.83,126.24
UTIL_3V3 on 09_PWR1: 240.03,174.65 240.03,14 129.49,14 126.47,17.02 79.63,17.02 77.57,19.08 67.56,19.08 64.57,16.08 58.27,16.08 56.18,14 13.74,14 13.74,5.74 1.27,5.74 1.27,174.65
UTIL_3V3 on 16_SIG5: 173.46,70.48 173.46,49.18 174.46,48.19 175.1,48.19 180.56,53.65 234.06,53.65 235.73,55.32 235.73,68.6 231.72,72.61 209.6,72.61 207.47,70.48
UTIL_3V3_FET_SWITCH on TOP (solid shape): 190.35,40.53 193.7,40.53 193.7,36.62 190.35,36.62 190.35,36.47 189.49,36.47 189.49,36.93 189.95,36.93 189.95,37.69 189.49,37.69 189.49,38.2 189.95,38.2 189.95,38.96 189.49,38.96 189.49,39.47 189.95,39.47 189.95,40.23 189.49,40.23 189.49,40.74 190.35,40.74
UTIL_3V3_FET_SWITCH on TOP (solid shape): 191.04,50.31 191.04,44.7 191.6,44.14 191.6,36.66 190.93,35.99 185.95,35.99 185.25,36.7 185.25,40.05 185.27,40.07 187.26,40.07 187.57,40.37 187.57,46.27 187.58,46.29 187.58,48.51 187.57,48.52 187.57,48.58 187.81,48.82 187.81,50.11 188.01,50.32 191.03,50.32
UTIL_3V3_FET_SWITCH on BOTTOM (solid shape): 191.11,44.7 191.11,36.17 190.93,35.99 188.06,35.99 187.58,36.47 187.58,43.11 189.56,45.08 190.73,45.08
UTIL_3V3_FET_SWITCH on 03_SIG1 (solid shape): 191.04,50.31 191.04,44.7 191.6,44.14 191.6,36.66 190.93,35.99 185.95,35.99 185.25,36.7 185.25,40.05 185.27,40.07 187.26,40.07 187.57,40.37 187.57,48.58 187.81,48.82 187.81,50.11 188.01,50.32 191.03,50.32
UTIL_3V3_FET_SWITCH on 05_SIG2 (solid shape): 191.04,50.31 191.04,44.7 191.6,44.14 191.6,36.66 190.93,35.99 185.95,35.99 185.25,36.7 185.25,40.05 185.27,40.07 187.26,40.07 187.57,40.37 187.57,48.58 187.81,48.82 187.81,50.11 188.01,50.32 191.03,50.32
UTIL_3V3_FET_SWITCH on 07_SIG3 (solid shape): 191.04,50.31 191.04,44.7 191.6,44.14 191.6,36.66 190.93,35.99 185.95,35.99 185.25,36.7 185.25,40.05 185.27,40.07 187.26,40.07 187.57,40.37 187.57,48.58 187.81,48.82 187.81,50.11 188.01,50.32 191.03,50.32
UTIL_3V3_FET_SWITCH on 14_SIG4 (solid shape): 191.04,50.31 191.04,44.7 191.6,44.14 191.6,36.66 190.93,35.99 185.95,35.99 185.25,36.7 185.25,40.05 185.27,40.07 187.26,40.07 187.57,40.37 187.57,48.58 187.81,48.82 187.81,50.11 188.01,50.32 191.03,50.32
UTIL_3V3_FET_SWITCH on 16_SIG5 (solid shape): 191.04,50.31 191.04,44.7 191.6,44.14 191.6,36.66 190.93,35.99 185.95,35.99 185.25,36.7 185.25,40.05 185.27,40.07 187.26,40.07 187.57,40.37 187.57,48.58 187.81,48.82 187.81,50.11 188.01,50.32 191.03,50.32
UTIL_3V3_FET_SWITCH on 18_SIG6 (solid shape): 191.04,50.31 191.04,44.7 191.6,44.14 191.6,36.66 190.93,35.99 185.95,35.99 185.25,36.7 185.25,40.05 185.27,40.07 187.26,40.07 187.57,40.37 187.57,48.58 187.81,48.82 187.81,50.11 188.01,50.32 191.03,50.32
UTIL_3V3_FET_SWITCH on 20_SIG7 (solid shape): 191.04,50.31 191.04,44.7 191.6,44.14 191.6,36.66 190.93,35.99 185.95,35.99 185.25,36.7 185.25,40.05 185.27,40.07 187.26,40.07 187.57,40.37 187.57,48.58 187.81,48.82 187.81,50.11 188.01,50.32 191.03,50.32
VADJ_1V8 on TOP (solid shape): outline of 105 points within 182.71,143.81 193.3,151.05
VADJ_1V8_FET_SWITCH on TOP (solid shape): 195.36,141.52 195.36,136.79 194.77,136.2 193.54,136.2 193.54,136.2 192.69,136.2 192.57,136.32 192.57,138.86 190.41,138.86 189.64,139.63 189.64,141.63 190.18,142.17 194.72,142.17
VADJ_1V8_FET_SWITCH on BOTTOM (solid shape): 195.36,136.2 193.54,136.2 193.54,136.2 192.69,136.2 192.57,136.32 192.57,138.86 190.41,138.86 189.57,139.7 188.96,139.7 187.92,140.74 187.92,142.17 195.36,142.17
VADJ_1V8_FET_SWITCH on 03_SIG1 (solid shape): 195.36,136.2 193.54,136.2 193.54,136.2 192.69,136.2 192.57,136.32 192.57,138.86 190.41,138.86 189.57,139.7 188.96,139.7 187.92,140.74 187.92,142.17 195.36,142.17
VADJ_1V8_FET_SWITCH on 05_SIG2 (solid shape): 195.36,136.2 193.54,136.2 193.54,136.2 192.69,136.2 192.57,136.32 192.57,138.86 190.41,138.86 189.57,139.7 188.96,139.7 187.92,140.74 187.92,142.17 195.36,142.17
VADJ_1V8_FET_SWITCH on 07_SIG3 (solid shape): 195.36,136.2 193.54,136.2 193.54,136.2 192.69,136.2 192.57,136.32 192.57,138.86 190.41,138.86 189.57,139.7 188.96,139.7 187.92,140.74 187.92,142.17 195.36,142.17
VADJ_1V8_FET_SWITCH on 14_SIG4 (solid shape): 195.36,136.2 193.54,136.2 193.54,136.2 192.69,136.2 192.57,136.32 192.57,138.86 190.41,138.86 189.57,139.7 188.96,139.7 187.92,140.74 187.92,142.17 195.36,142.17
VADJ_1V8_FET_SWITCH on 16_SIG5 (solid shape): 195.36,136.2 193.54,136.2 193.54,136.2 192.69,136.2 192.57,136.32 192.57,138.86 190.41,138.86 189.57,139.7 188.96,139.7 187.92,140.74 187.92,142.17 195.36,142.17
VADJ_1V8_FET_SWITCH on 18_SIG6 (solid shape): 195.36,136.2 193.54,136.2 193.54,136.2 192.69,136.2 192.57,136.32 192.57,138.86 190.41,138.86 189.57,139.7 188.96,139.7 187.92,140.74 187.92,142.17 195.36,142.17
VADJ_1V8_FET_SWITCH on 20_SIG7 (solid shape): 195.36,136.2 193.54,136.2 193.54,136.2 192.69,136.2 192.57,136.32 192.57,138.86 190.41,138.86 189.57,139.7 188.96,139.7 187.92,140.74 187.92,142.17 195.36,142.17
VADJ_1V8_FPGA on TOP (solid shape): outline of 136 points within 192.15,141.5 199.64,150.44
VADJ_1V8_FPGA on BOTTOM (solid shape): 197.19,150.05 197.19,144.48 193.58,144.48 193.58,147.06 192.15,148.49 192.15,150.24 192.36,150.45 196.78,150.45
VADJ_1V8_FPGA on 03_SIG1: 55.37,174.65 184.61,174.65 191.36,167.89 191.36,160.93 200.84,151.46 200.84,143.48 198.22,140.87 196.49,140.87 195.99,141.38 195.99,142.49 195.45,143.03 178.66,143.03 173.69,148.01 144.81,148.01 134.87,157.94 119.89,157.94 116.54,161.29 87.38,161.29 84.84,163.83 68.22,163.83 66.95,162.56 57.02,162.56 56.79,162.33 56.79,161.72 55.4,163.12 55.4,167.56 57.18,169.34 57.18,170.92 54.43,170.92 54.38,170.97 54.38,173.66
VADJ_1V8_FPGA on 05_SIG2: 48.13,173.91 48.13,158.62 63.96,158.62 63.96,173.91
VADJ_1V8_FPGA on 11_PWR2: 197.28,150.77 198.88,149.17 198.88,136.68 189.31,127.1 189.31,77.14 179.4,67.23 179.4,46.41 172.62,39.62 134.04,39.62 133.64,40.02 133.64,49.36 130.43,52.58 122.76,52.58 121.82,53.52 112.73,53.52 111.4,52.2 104.19,52.2 102.97,53.42 102.97,78.74 105.92,81.69 108.58,81.69 113.92,76.35 113.92,73.99 112.98,73.05 110.82,73.05 110.16,72.39 110.16,69.34 114.73,64.77 121.11,64.77 127.71,58.17 139.8,58.17 140.59,57.38 159.33,57.38 161.16,59.21 161.16,126.42 156.06,131.52 143,131.52 139.85,128.37 139.85,123.83 142.62,121.06 142.62,74.57 139.78,71.73 124.87,71.73 122.63,73.96 122.63,77.19 126.24,80.8 128.45,80.8 129.97,82.32 129.97,89.71 123.81,95.87 123.81,127.01 138.02,141.22 165.66,141.22 170.64,136.25 175.26,136.25 180.97,141.96 180.97,145.36 186.39,150.77

Small or netless copper shapes (teardrops, artwork), in the pictures only: 213 on TOP, 200 on BOTTOM

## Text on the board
BOTTOM: BFRLVEEM | UL94V0 | PCB P/N 1280906
Ref Des/Silkscreen Bottom: BFRLPKVESCEM | IIC EEPROM | 7 | 1 | 9 | 3 | A | E | K | R | T | FPGA | SD Card | QSPI FLASH | DDR4 C1 COMPONENTS
User.Comments: CR_UNNAMED_8 | CR_00_1 | CR_1_10 | CR_UNNAMED_10 | CR_UNNAMED_9 | CR_22_1 | CR_FIN_1 | CR_1_6 | CR_100_1 | CR_01_1 | CR_0_2 | CR_1_8 | CR_2_2 | CR_1_9 | CR_0_1 | CR_1_1 | CR_1_7 | CR_1_2 | CR_10_1 | CR_10_2 | CR_000_1 | CR_CLK_1 | CR_00_2
Ref Des/Assembly Top: BPI FLASH
Ref Des/Silkscreen Top: MGTAVCC | MGTAVTT | MGTVCCAUX | MAC ID | USB UART | USB JTAG | ERR | SYS_1V0 | U111 BOOTMODE | M3 | M2 | M1 | M0 | TMS | TCK | TDO | TDI | S | M | SYS_1V8 | 3 | 7 | 1 | T | 9 | R | USER_CLK_N | RLD3 Components | E | A | USER_CLK_P | PCIE FINGER 16X | N | CPU_RESET | USER_CLOCK | L | VADJ INH | U | VCC1V8 | DDR4_C2_VTT | VCCINTIO_BRAM | VCC12 | VADJ_1V8 | POR_OVERRIDE | PGOOD | 6 | 5 | 4 | GPIO LEDs | 2 | 0 | INIT | GPIO | MOMENTARY | DONE | +12V | VCC1V2 | 1.8V | VADJ | 1.2V | SYSDONE | STAT | SYSINIT | MGT226_CLK0_P | PCIe Test | SYSCON_POR | FM0 | FM1 | FM2 | SYS | EN | MGT226_CLK0_N | PHY1_RESET_B | 10/100/1000 ETHERNET | UTIL_1V35 | MGT233_CLK1_P | MGT233_CLK1_N | SYS_2V2 | GPIO DIP SW | RLD3_C3_VTERM_0V6 | DDR4_C1_VTT | SYS_2V5 | K | 3.3V | SYSCLK | 12V FAN | INT | VCCINT | UTIL_3V3 | REG INH | REV2.0 | HW-U1-VCU118 | H | J | QSFP+ | D | G | P | Q | PROG | FMC HPC | FMC HPC1 | C | QSPI FLASH | BATT | B | PMOD | DDR4 C2 COMPONENTS | PMBus
XSECTION_CHART: *  SURFACE - AIR 0 MIL | L1: TOP CONDUCTOR - COPPER 2 MIL | *  DIELECTRIC - MEG6_PREG_1-1078 3.35 MIL | L2: 02_GND PLANE - COPPER 0.6 MIL | *  DIELECTRIC - MEG6_CORE_2-1078 5.8 MIL | L3: 03_SIG1 CONDUCTOR - COPPER 0.6 MIL | *  DIELECTRIC - MEG6_PREG_2-3313 7.2 MIL | L4: 04_GND PLANE - COPPER 0.6 MIL | L5: 05_SIG2 CONDUCTOR - COPPER 0.6 MIL | L6: 06_GND PLANE - COPPER 0.6 MIL | L7: 07_SIG3 CONDUCTOR - COPPER 0.6 MIL | L8: 08_GND PLANE - COPPER 0.6 MIL | L9: 09_PWR1 PLANE - COPPER 0.6 MIL | L10: 10_GND PLANE - COPPER 1.7 MIL | *  DIELECTRIC - MEG6_PREG_2-1035 4.54 MIL | L11: 11_PWR2 PLANE - COPPER 1.7 MIL | L12: 12_PWR3 PLANE - COPPER 0.6 MIL | *  DIELECTRIC - MEG6_CORE_1-1078 3 MIL | L13: 13_GND PLANE - COPPER 0.6 MIL | *  DIELECTRIC - MEG6_PREG_1-1078 3.8 MIL | L14: 14_SIG4 CONDUCTOR - COPPER 0.6 MIL | L15: 15_GND PLANE - COPPER 0.6 MIL | L16: 16_SIG5 CONDUCTOR - COPPER 0.6 MIL | L17: 17_GND PLANE - COPPER 0.6 MIL | L18: 18_SIG6 CONDUCTOR - COPPER 0.6 MIL | L19: 19_GND PLANE - COPPER 0.6 MIL | L20: 20_SIG7 CONDUCTOR - COPPER 0.6 MIL | L21: 21_GND PLANE - COPPER 0.6 MIL | L22: BOTTOM CONDUCTOR - COPPER 2 MIL | DESIGN CROSS SECTION CHART | ___________________________ | TOTAL THICKNESS 111.14 MIL | 1-10 | 1-22
DIMENSION: +0,25 | - | +,010 | 0,051 | 1,30 | 1.57 | 0.062 | MAX OVER PLATING | 20 | .033 | .060 | 4xSLOT:.033x.026 | 4xSLOT:.060x.032 | .026 | .032 | .591 | .144 | .459 | 2.250 | 1.955 | R.037 | 9.500 | .200 | [ | ] | SEE DETAIL"A" | PRESS FIT | DETAIL"A" | R.072 | 6.927 | 6.751 | 5.386 | 3.362 | .191 | .325 | .286 | .152 | 6.064 | 4x45 X.020
PAGE_OUTLINE: R | REV | 2.0 | DESCRIPTION | PROTOTYPE | 07/14/17 | DATE | APPROVED | 4 | 3 | DIMENSIONS ARE IN INCHES | TOLERANCES ON; | 2 PL DECIMALS +/- .010 | 3 PL DECIMALS +/- .005 | ANGLES + | FRACTIONS + | DRAWN | CHECKED | ENGRG | ISSUED | SCALE | SIZE | FSCM NO | DWG NO | REVISIONS | SHEET | NONE | UNLESS OTHERWISE SPECIFIED | SIGNATURES | SAN JOSE, CA 95124 | 2100 LOGIC DR. | HWCP - HARDWARE & CONFIGURATION PLATFORMS | 07-14-17 | Lou Morrison | D | C | B | A | 7 | 6 | 5 | 2 | 1
